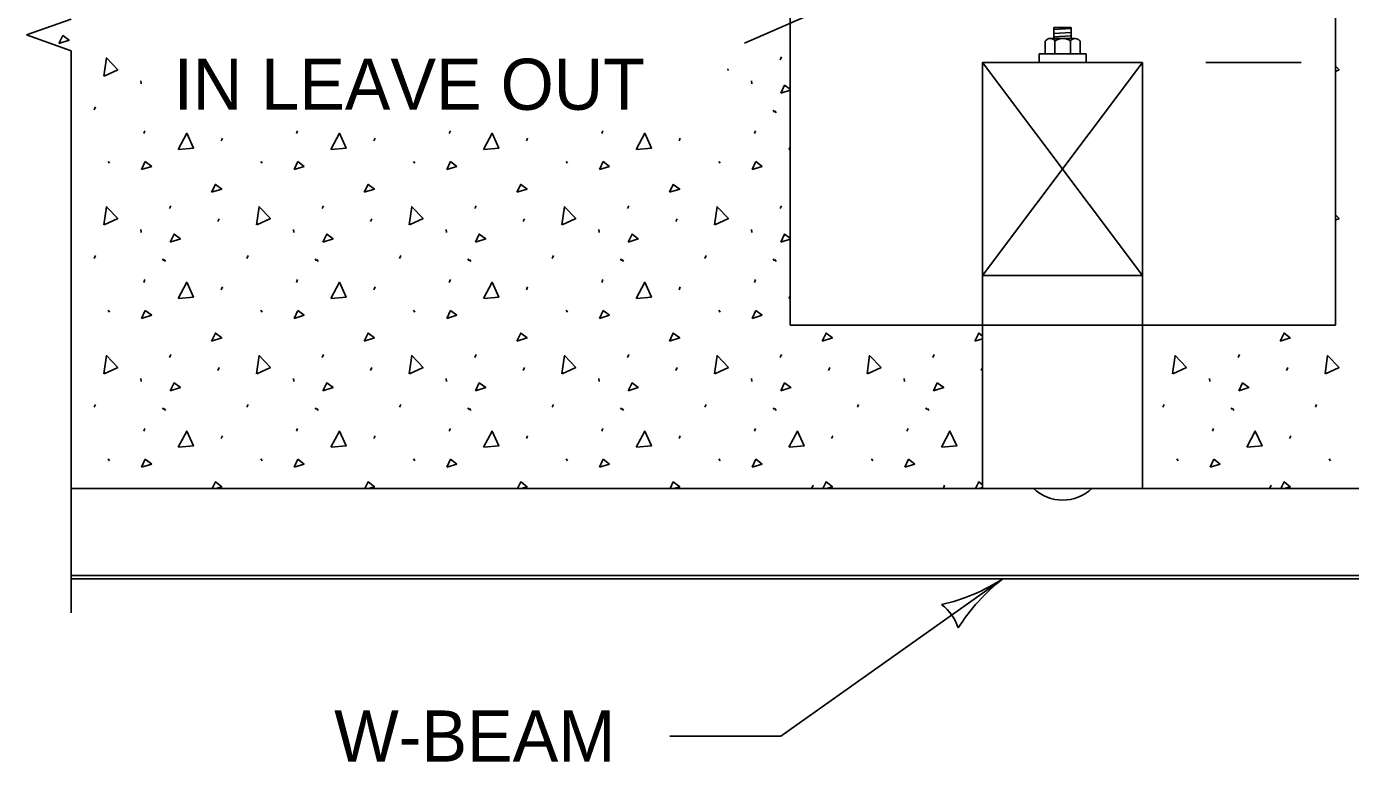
# Model space of a CAD drawing. Extents: x 49991.4 to 50021, y 49987.6 to 50011.4.
# Drawn here: x 50009.655 to 50011.209, y 49995.289 to 49996.152 of the extents above; entities that cross this region are included whole.
import ezdxf

# ---------------------------------------------------------------- set-up
doc = ezdxf.new("R2010")
doc.units = 0
for name, color, linetype in [('Level 1', 7, 'Continuous'), ('Level 2', 7, 'Continuous'), ('Level 3', 7, 'Continuous'), ('Level 4', 7, 'Continuous'), ('Level 6', 7, 'Continuous')]:
    doc.layers.add(name, color=color, linetype=linetype)

msp = doc.modelspace()

# ---------------------------------------------------------------- linework, layer by layer
at = {"layer": 'Level 1'}
for p, q in [((50010.5512, 49996.1214), (50010.5512, 49996.4414)), ((50011.1912, 49996.1214), (50011.1912, 49996.4414)), ((50010.8813, 49996.1506), (50010.8607, 49996.1506)), ((50010.8607, 49996.1379), (50010.8607, 49996.1506)), ((50010.8813, 49996.1494), (50010.8607, 49996.1484)), ((50010.8813, 49996.1378), (50010.8813, 49996.1506)), ((50010.8507, 49996.1198), (50010.8507, 49996.1348)), ((50010.8859, 49996.1378), (50010.8565, 49996.1379)), ((50010.8813, 49996.1449), (50010.8607, 49996.1438)), ((50010.8813, 49996.1408), (50010.8607, 49996.1398)), ((50010.8621, 49996.1198), (50010.8621, 49996.1349)), ((50010.8803, 49996.1198), (50010.8803, 49996.135)), ((50010.8915, 49996.1352), (50010.8915, 49996.1198)), ((50010.5396, 49996.1128), (50010.5411, 49996.1162)), ((50010.5512, 49996.1214), (50010.5512, 49995.8014)), ((50010.8986, 49996.1198), (50010.8436, 49996.1198)), ((50010.8436, 49996.1198), (50010.8436, 49996.1097)), ((50010.8986, 49996.1198), (50010.8986, 49996.1097)), ((50011.1912, 49996.1214), (50011.1912, 49995.8014)), ((50010.7772, 49995.6094), (50010.7772, 49996.1097)), ((50010.9648, 49996.1097), (50010.7772, 49996.1097)), ((50010.7772, 49996.1097), (50010.9648, 49995.8595)), ((50010.9648, 49996.1097), (50010.7772, 49995.8595)), ((50010.9648, 49995.6094), (50010.9648, 49996.1097)), ((50009.7892, 49996.0881), (50009.7896, 49996.0848)), ((50010.5058, 49996.0881), (50010.5062, 49996.0848)), ((50010.5512, 49996.077), (50010.5404, 49996.0736)), ((50009.7345, 49996.0542), (50009.736, 49996.0576)), ((50010.5313, 49996.0537), (50010.5328, 49996.0515)), ((50010.5333, 49996.0529), (50010.5348, 49996.0507)), ((50009.7926, 49996.0261), (50009.7941, 49996.0295)), ((50009.8834, 49996.0175), (50009.8849, 49996.0209)), ((50009.9718, 49996.0261), (50009.9733, 49996.0295)), ((50010.0626, 49996.0175), (50010.0641, 49996.0209)), ((50010.151, 49996.0261), (50010.1525, 49996.0295)), ((50010.2417, 49996.0175), (50010.2432, 49996.0209)), ((50010.3301, 49996.0261), (50010.3316, 49996.0295)), ((50010.4209, 49996.0175), (50010.4224, 49996.0209)), ((50010.5093, 49996.0261), (50010.5108, 49996.0295)), ((50010.5497, 49996.0074), (50010.5512, 49996.0104)), ((50010.5512, 49996.0075), (50010.5501, 49996.0074)), ((50009.7509, 49995.9936), (50009.7524, 49995.9914)), ((50009.79, 49995.9839), (50009.7945, 49995.9933)), ((50009.7945, 49995.9933), (50009.802, 49995.9877)), ((50009.93, 49995.9936), (50009.9315, 49995.9914)), ((50009.9692, 49995.9839), (50009.9737, 49995.9933)), ((50009.9737, 49995.9933), (50009.9811, 49995.9877)), ((50010.1092, 49995.9936), (50010.1107, 49995.9914)), ((50010.1483, 49995.9839), (50010.1528, 49995.9933)), ((50010.1528, 49995.9933), (50010.1603, 49995.9877)), ((50010.2883, 49995.9936), (50010.2898, 49995.9914)), ((50010.3275, 49995.9839), (50010.332, 49995.9933)), ((50010.332, 49995.9933), (50010.3394, 49995.9877)), ((50010.4675, 49995.9936), (50010.469, 49995.9914)), ((50010.5067, 49995.9839), (50010.5111, 49995.9933)), ((50010.5111, 49995.9933), (50010.5186, 49995.9877)), ((50009.802, 49995.9877), (50009.79, 49995.9839)), ((50009.9811, 49995.9877), (50009.9692, 49995.9839)), ((50010.1603, 49995.9877), (50010.1483, 49995.9839)), ((50010.3394, 49995.9877), (50010.3275, 49995.9839)), ((50010.5186, 49995.9877), (50010.5067, 49995.9839)), ((50009.823, 49995.9381), (50009.8245, 49995.9414)), ((50010.0021, 49995.9381), (50010.0036, 49995.9414)), ((50010.1813, 49995.9381), (50010.1828, 49995.9414)), ((50010.3605, 49995.9381), (50010.362, 49995.9414)), ((50010.5396, 49995.9381), (50010.5411, 49995.9414)), ((50009.7892, 49995.9134), (50009.7896, 49995.9101)), ((50009.8797, 49995.9228), (50009.8812, 49995.9261)), ((50009.9684, 49995.9134), (50009.9687, 49995.9101)), ((50010.0588, 49995.9228), (50010.0603, 49995.9261)), ((50010.1475, 49995.9134), (50010.1479, 49995.9101)), ((50010.238, 49995.9228), (50010.2395, 49995.9261)), ((50010.3267, 49995.9134), (50010.327, 49995.9101)), ((50010.4172, 49995.9228), (50010.4186, 49995.9261)), ((50010.5058, 49995.9134), (50010.5062, 49995.9101)), ((50010.5512, 49995.9023), (50010.5404, 49995.8989)), ((50009.7345, 49995.8795), (50009.736, 49995.8829)), ((50009.9136, 49995.8795), (50009.9151, 49995.8829)), ((50010.0928, 49995.8795), (50010.0943, 49995.8829)), ((50010.2719, 49995.8795), (50010.2734, 49995.8829)), ((50010.4511, 49995.8795), (50010.4526, 49995.8829)), ((50009.8146, 49995.879), (50009.8161, 49995.8768)), ((50009.8166, 49995.8782), (50009.8181, 49995.8759)), ((50009.9938, 49995.879), (50009.9953, 49995.8768)), ((50009.9958, 49995.8782), (50009.9973, 49995.8759)), ((50010.173, 49995.879), (50010.1745, 49995.8768)), ((50010.175, 49995.8782), (50010.1765, 49995.8759)), ((50010.3521, 49995.879), (50010.3536, 49995.8768)), ((50010.3541, 49995.8782), (50010.3556, 49995.8759)), ((50010.5313, 49995.879), (50010.5328, 49995.8768)), ((50010.5333, 49995.8782), (50010.5348, 49995.8759)), ((50009.7926, 49995.8514), (50009.7941, 49995.8547)), ((50009.9718, 49995.8514), (50009.9733, 49995.8547)), ((50010.151, 49995.8514), (50010.1525, 49995.8547)), ((50010.3301, 49995.8514), (50010.3316, 49995.8547)), ((50010.5093, 49995.8514), (50010.5108, 49995.8547)), ((50010.9648, 49995.8595), (50010.7772, 49995.8595)), ((50009.8834, 49995.8428), (50009.8849, 49995.8462)), ((50010.0626, 49995.8428), (50010.0641, 49995.8462)), ((50010.2417, 49995.8428), (50010.2432, 49995.8462)), ((50010.4209, 49995.8428), (50010.4224, 49995.8462)), ((50010.5497, 49995.8327), (50010.5512, 49995.8357)), ((50009.7509, 49995.8189), (50009.7524, 49995.8167)), ((50009.93, 49995.8189), (50009.9315, 49995.8167)), ((50010.1092, 49995.8189), (50010.1107, 49995.8167)), ((50010.2883, 49995.8189), (50010.2898, 49995.8167)), ((50010.4675, 49995.8189), (50010.469, 49995.8167)), ((50010.5512, 49995.8328), (50010.5501, 49995.8327)), ((50009.79, 49995.8092), (50009.7945, 49995.8186)), ((50009.802, 49995.813), (50009.79, 49995.8092)), ((50009.7945, 49995.8186), (50009.802, 49995.813)), ((50009.9692, 49995.8092), (50009.9737, 49995.8186)), ((50009.9811, 49995.813), (50009.9692, 49995.8092)), ((50009.9737, 49995.8186), (50009.9811, 49995.813)), ((50010.1483, 49995.8092), (50010.1528, 49995.8186)), ((50010.1603, 49995.813), (50010.1483, 49995.8092)), ((50010.1528, 49995.8186), (50010.1603, 49995.813)), ((50010.3275, 49995.8092), (50010.332, 49995.8186)), ((50010.3394, 49995.813), (50010.3275, 49995.8092)), ((50010.332, 49995.8186), (50010.3394, 49995.813)), ((50010.5067, 49995.8092), (50010.5111, 49995.8186)), ((50010.5186, 49995.813), (50010.5067, 49995.8092)), ((50010.5111, 49995.8186), (50010.5186, 49995.813)), ((50010.7772, 49995.8014), (50010.5512, 49995.8014)), ((50010.9648, 49995.8014), (50011.1912, 49995.8014)), ((50010.9648, 49995.6121), (50010.9648, 49995.7954)), ((50010.7772, 49995.7854), (50010.7681, 49995.7826)), ((50009.823, 49995.7634), (50009.8245, 49995.7667)), ((50010.0021, 49995.7634), (50010.0036, 49995.7667)), ((50010.1813, 49995.7634), (50010.1828, 49995.7667)), ((50010.3605, 49995.7634), (50010.362, 49995.7667)), ((50010.5396, 49995.7634), (50010.5411, 49995.7667)), ((50010.7188, 49995.7634), (50010.7203, 49995.7667)), ((50011.0771, 49995.7634), (50011.0786, 49995.7667)), ((50009.8797, 49995.7481), (50009.8812, 49995.7514)), ((50010.0588, 49995.7481), (50010.0603, 49995.7514)), ((50010.238, 49995.7481), (50010.2395, 49995.7514)), ((50010.4172, 49995.7481), (50010.4186, 49995.7514)), ((50010.5963, 49995.7481), (50010.5978, 49995.7514)), ((50010.7755, 49995.7481), (50010.777, 49995.7514)), ((50011.1338, 49995.7481), (50011.1353, 49995.7514)), ((50009.7892, 49995.7387), (50009.7896, 49995.7353)), ((50009.9684, 49995.7387), (50009.9687, 49995.7353)), ((50010.1475, 49995.7387), (50010.1479, 49995.7353)), ((50010.3267, 49995.7387), (50010.327, 49995.7353)), ((50010.5058, 49995.7387), (50010.5062, 49995.7353)), ((50010.685, 49995.7387), (50010.6854, 49995.7353)), ((50011.0433, 49995.7387), (50011.0437, 49995.7353)), ((50009.7345, 49995.7048), (50009.736, 49995.7082)), ((50009.8146, 49995.7043), (50009.8161, 49995.7021)), ((50009.8166, 49995.7034), (50009.8181, 49995.7012)), ((50009.9136, 49995.7048), (50009.9151, 49995.7082)), ((50009.9938, 49995.7043), (50009.9953, 49995.7021)), ((50009.9958, 49995.7034), (50009.9973, 49995.7012)), ((50010.0928, 49995.7048), (50010.0943, 49995.7082)), ((50010.173, 49995.7043), (50010.1745, 49995.7021)), ((50010.175, 49995.7034), (50010.1765, 49995.7012)), ((50010.2719, 49995.7048), (50010.2734, 49995.7082)), ((50010.3521, 49995.7043), (50010.3536, 49995.7021)), ((50010.3541, 49995.7034), (50010.3556, 49995.7012)), ((50010.4511, 49995.7048), (50010.4526, 49995.7082)), ((50010.5313, 49995.7043), (50010.5328, 49995.7021)), ((50010.5333, 49995.7034), (50010.5348, 49995.7012)), ((50010.6303, 49995.7048), (50010.6317, 49995.7082)), ((50010.7104, 49995.7043), (50010.7119, 49995.7021)), ((50010.7124, 49995.7034), (50010.7139, 49995.7012)), ((50010.9886, 49995.7048), (50010.9901, 49995.7082)), ((50011.0688, 49995.7043), (50011.0703, 49995.7021)), ((50011.0708, 49995.7034), (50011.0722, 49995.7012)), ((50011.1677, 49995.7048), (50011.1692, 49995.7082)), ((50009.7926, 49995.6767), (50009.7941, 49995.68)), ((50009.9718, 49995.6767), (50009.9733, 49995.68)), ((50010.151, 49995.6767), (50010.1525, 49995.68)), ((50010.3301, 49995.6767), (50010.3316, 49995.68)), ((50010.5093, 49995.6767), (50010.5108, 49995.68)), ((50010.6884, 49995.6767), (50010.6899, 49995.68)), ((50011.0468, 49995.6767), (50011.0482, 49995.68)), ((50009.8834, 49995.6681), (50009.8849, 49995.6714)), ((50010.0626, 49995.6681), (50010.0641, 49995.6714)), ((50010.2417, 49995.6681), (50010.2432, 49995.6714)), ((50010.4209, 49995.6681), (50010.4224, 49995.6714)), ((50010.6, 49995.6681), (50010.6015, 49995.6714)), ((50011.1375, 49995.6681), (50011.139, 49995.6714)), ((50009.7509, 49995.6442), (50009.7524, 49995.642)), ((50009.79, 49995.6345), (50009.7945, 49995.6438)), ((50009.802, 49995.6382), (50009.79, 49995.6345)), ((50009.7945, 49995.6438), (50009.802, 49995.6382)), ((50009.93, 49995.6442), (50009.9315, 49995.642)), ((50009.9692, 49995.6345), (50009.9737, 49995.6438)), ((50009.9811, 49995.6382), (50009.9692, 49995.6345)), ((50009.9737, 49995.6438), (50009.9811, 49995.6382)), ((50010.1092, 49995.6442), (50010.1107, 49995.642)), ((50010.1483, 49995.6345), (50010.1528, 49995.6438)), ((50010.1603, 49995.6382), (50010.1483, 49995.6345)), ((50010.1528, 49995.6438), (50010.1603, 49995.6382)), ((50010.2883, 49995.6442), (50010.2898, 49995.642)), ((50010.3275, 49995.6345), (50010.332, 49995.6438)), ((50010.3394, 49995.6382), (50010.3275, 49995.6345)), ((50010.332, 49995.6438), (50010.3394, 49995.6382)), ((50010.4675, 49995.6442), (50010.469, 49995.642)), ((50010.5067, 49995.6345), (50010.5111, 49995.6438)), ((50010.5186, 49995.6382), (50010.5067, 49995.6345)), ((50010.5111, 49995.6438), (50010.5186, 49995.6382)), ((50010.6467, 49995.6442), (50010.6482, 49995.642)), ((50010.6858, 49995.6345), (50010.6903, 49995.6438)), ((50010.6978, 49995.6382), (50010.6858, 49995.6345)), ((50010.6903, 49995.6438), (50010.6978, 49995.6382)), ((50011.005, 49995.6442), (50011.0065, 49995.642)), ((50011.0441, 49995.6345), (50011.0486, 49995.6438)), ((50011.0561, 49995.6382), (50011.0441, 49995.6345)), ((50011.0486, 49995.6438), (50011.0561, 49995.6382)), ((50011.1841, 49995.6442), (50011.1856, 49995.642)), ((50009.9073, 49995.6094), (50009.7073, 49995.6094)), ((50009.9073, 49995.6094), (50011.8351, 49995.6094)), ((50010.5769, 49995.61), (50010.5784, 49995.6134)), ((50010.7311, 49995.61), (50010.7326, 49995.6134)), ((50010.7772, 49995.6107), (50010.7731, 49995.6094)), ((50011.1144, 49995.61), (50011.1159, 49995.6134)), ((50009.7073, 49995.5073), (50012.0351, 49995.5073)), ((50009.7073, 49995.5034), (50012.0351, 49995.5034))]:
    msp.add_line(p, q, dxfattribs=at)
for points in [[(50009.6931, 49996.132), (50009.6976, 49996.1413), (50009.7051, 49996.1357), (50009.6931, 49996.132)], [(50009.7459, 49996.0936), (50009.7488, 49996.115), (50009.7622, 49996.1012), (50009.7462, 49996.0938)], [(50010.4779, 49996.1021), (50010.4788, 49996.1012), (50010.4779, 49996.1007)], [(50011.1912, 49996.1055), (50011.1955, 49996.1012), (50011.1912, 49996.0992)], [(50010.5404, 49996.0736), (50010.5448, 49996.083), (50010.5512, 49996.0782)], [(50009.8331, 49996.0074), (50009.8431, 49996.0265), (50009.851, 49996.0089), (50009.8334, 49996.0074)], [(50010.0122, 49996.0074), (50010.0223, 49996.0265), (50010.0301, 49996.0089), (50010.0126, 49996.0074)], [(50010.1914, 49996.0074), (50010.2014, 49996.0265), (50010.2093, 49996.0089), (50010.1917, 49996.0074)], [(50010.3705, 49996.0074), (50010.3806, 49996.0265), (50010.3884, 49996.0089), (50010.3709, 49996.0074)], [(50009.8723, 49995.9573), (50009.8768, 49995.9666), (50009.8842, 49995.961), (50009.8723, 49995.9573)], [(50010.0515, 49995.9573), (50010.0559, 49995.9666), (50010.0634, 49995.961), (50010.0515, 49995.9573)], [(50010.2306, 49995.9573), (50010.2351, 49995.9666), (50010.2425, 49995.961), (50010.2306, 49995.9573)], [(50010.4098, 49995.9573), (50010.4142, 49995.9666), (50010.4217, 49995.961), (50010.4098, 49995.9573)], [(50009.7459, 49995.9189), (50009.7488, 49995.9402), (50009.7622, 49995.9264), (50009.7462, 49995.919)], [(50009.9251, 49995.9189), (50009.928, 49995.9402), (50009.9414, 49995.9264), (50009.9254, 49995.919)], [(50010.1042, 49995.9189), (50010.1072, 49995.9402), (50010.1205, 49995.9264), (50010.1046, 49995.919)], [(50010.2834, 49995.9189), (50010.2863, 49995.9402), (50010.2997, 49995.9264), (50010.2837, 49995.919)], [(50010.4625, 49995.9189), (50010.4655, 49995.9402), (50010.4788, 49995.9264), (50010.4629, 49995.919)], [(50011.1912, 49995.9308), (50011.1955, 49995.9264), (50011.1912, 49995.9245)], [(50009.8237, 49995.8989), (50009.8282, 49995.9082), (50009.8357, 49995.9026), (50009.8237, 49995.8989)], [(50010.0029, 49995.8989), (50010.0074, 49995.9082), (50010.0148, 49995.9026), (50010.0029, 49995.8989)], [(50010.1821, 49995.8989), (50010.1865, 49995.9082), (50010.194, 49995.9026), (50010.1821, 49995.8989)], [(50010.3612, 49995.8989), (50010.3657, 49995.9082), (50010.3731, 49995.9026), (50010.3612, 49995.8989)], [(50010.5404, 49995.8989), (50010.5448, 49995.9082), (50010.5512, 49995.9034)], [(50009.8331, 49995.8327), (50009.8431, 49995.8517), (50009.851, 49995.8342), (50009.8334, 49995.8327)], [(50010.0122, 49995.8327), (50010.0223, 49995.8517), (50010.0301, 49995.8342), (50010.0126, 49995.8327)], [(50010.1914, 49995.8327), (50010.2014, 49995.8517), (50010.2093, 49995.8342), (50010.1917, 49995.8327)], [(50010.3705, 49995.8327), (50010.3806, 49995.8517), (50010.3884, 49995.8342), (50010.3709, 49995.8327)], [(50009.8723, 49995.7826), (50009.8768, 49995.7919), (50009.8842, 49995.7863), (50009.8723, 49995.7826)], [(50010.0515, 49995.7826), (50010.0559, 49995.7919), (50010.0634, 49995.7863), (50010.0515, 49995.7826)], [(50010.2306, 49995.7826), (50010.2351, 49995.7919), (50010.2425, 49995.7863), (50010.2306, 49995.7826)], [(50010.4098, 49995.7826), (50010.4142, 49995.7919), (50010.4217, 49995.7863), (50010.4098, 49995.7826)], [(50010.5889, 49995.7826), (50010.5934, 49995.7919), (50010.6009, 49995.7863), (50010.5889, 49995.7826)], [(50010.7681, 49995.7826), (50010.7726, 49995.7919), (50010.7772, 49995.7884)], [(50011.1264, 49995.7826), (50011.1309, 49995.7919), (50011.1383, 49995.7863), (50011.1264, 49995.7826)], [(50009.7459, 49995.7442), (50009.7488, 49995.7655), (50009.7622, 49995.7517), (50009.7462, 49995.7443)], [(50009.9251, 49995.7442), (50009.928, 49995.7655), (50009.9414, 49995.7517), (50009.9254, 49995.7443)], [(50010.1042, 49995.7442), (50010.1072, 49995.7655), (50010.1205, 49995.7517), (50010.1046, 49995.7443)], [(50010.2834, 49995.7442), (50010.2863, 49995.7655), (50010.2997, 49995.7517), (50010.2837, 49995.7443)], [(50010.4625, 49995.7442), (50010.4655, 49995.7655), (50010.4788, 49995.7517), (50010.4629, 49995.7443)], [(50010.6417, 49995.7442), (50010.6446, 49995.7655), (50010.658, 49995.7517), (50010.642, 49995.7443)], [(50011, 49995.7442), (50011.003, 49995.7655), (50011.0163, 49995.7517), (50011.0004, 49995.7443)], [(50011.1792, 49995.7442), (50011.1821, 49995.7655), (50011.1955, 49995.7517), (50011.1795, 49995.7443)], [(50009.8237, 49995.7242), (50009.8282, 49995.7335), (50009.8357, 49995.7279), (50009.8237, 49995.7242)], [(50010.0029, 49995.7242), (50010.0074, 49995.7335), (50010.0148, 49995.7279), (50010.0029, 49995.7242)], [(50010.1821, 49995.7242), (50010.1865, 49995.7335), (50010.194, 49995.7279), (50010.1821, 49995.7242)], [(50010.3612, 49995.7242), (50010.3657, 49995.7335), (50010.3731, 49995.7279), (50010.3612, 49995.7242)], [(50010.5404, 49995.7242), (50010.5448, 49995.7335), (50010.5523, 49995.7279), (50010.5404, 49995.7242)], [(50010.7195, 49995.7242), (50010.724, 49995.7335), (50010.7315, 49995.7279), (50010.7195, 49995.7242)], [(50011.0778, 49995.7242), (50011.0823, 49995.7335), (50011.0898, 49995.7279), (50011.0778, 49995.7242)], [(50009.8331, 49995.658), (50009.8431, 49995.677), (50009.851, 49995.6595), (50009.8334, 49995.658)], [(50010.0122, 49995.658), (50010.0223, 49995.677), (50010.0301, 49995.6595), (50010.0126, 49995.658)], [(50010.1914, 49995.658), (50010.2014, 49995.677), (50010.2093, 49995.6595), (50010.1917, 49995.658)], [(50010.3705, 49995.658), (50010.3806, 49995.677), (50010.3884, 49995.6595), (50010.3709, 49995.658)], [(50010.5497, 49995.658), (50010.5598, 49995.677), (50010.5676, 49995.6595), (50010.5501, 49995.658)], [(50010.7289, 49995.658), (50010.7389, 49995.677), (50010.7468, 49995.6595), (50010.7292, 49995.658)], [(50011.0872, 49995.658), (50011.0972, 49995.677), (50011.1051, 49995.6595), (50011.0875, 49995.658)], [(50009.873, 49995.6094), (50009.8768, 49995.6172), (50009.8842, 49995.6116), (50009.8773, 49995.6094)], [(50010.0522, 49995.6094), (50010.0559, 49995.6172), (50010.0634, 49995.6116), (50010.0565, 49995.6094)], [(50010.2314, 49995.6094), (50010.2351, 49995.6172), (50010.2425, 49995.6116), (50010.2356, 49995.6094)], [(50010.4105, 49995.6094), (50010.4142, 49995.6172), (50010.4217, 49995.6116), (50010.4148, 49995.6094)], [(50010.5897, 49995.6094), (50010.5934, 49995.6172), (50010.6009, 49995.6116), (50010.594, 49995.6094)], [(50010.7688, 49995.6094), (50010.7726, 49995.6172), (50010.7772, 49995.6137)], [(50011.1272, 49995.6094), (50011.1309, 49995.6172), (50011.1383, 49995.6116), (50011.1314, 49995.6094)]]:
    msp.add_lwpolyline(points, dxfattribs=at)
for centre, major_axis, start_param, end_param in [((50010.8565, 49996.1311), (0.00683, 0), 0.591441, 2.573965), ((50010.8713, 49996.1224), (-0.0156, 0), 4.094675, 5.339631), ((50010.8859, 49996.1308), (-0.00704, 0), 3.808999, 5.646245)]:
    msp.add_ellipse(centre, major_axis=major_axis, ratio=0.991667, start_param=start_param, end_param=end_param, dxfattribs=at)
at = {"layer": 'Level 3'}
for p, q in [((50010.8713, 49996.296), (50010.4979, 49996.1323)), ((50011.1512, 49996.1097), (50011.0391, 49996.1097)), ((50010.5404, 49995.3189), (50010.8008, 49995.5034)), ((50010.41, 49995.3189), (50010.5404, 49995.3189))]:
    msp.add_line(p, q, dxfattribs=at)
for centre, radius, start, end in [((50010.6799, 49995.69), 0.2223, 282.7682, 302.9517), ((50010.9447, 49995.3202), 0.233, 128.1395, 147.3894), ((50010.6962, 49995.4293), 0.0548, 17.451, 53.1734)]:
    msp.add_arc(centre, radius, start, end, dxfattribs=at)
at = {"layer": 'Level 4'}
msp.add_line((50010.7772, 49995.8014), (50010.9648, 49995.8014), dxfattribs=at)
msp.add_ellipse((50010.8712, 49995.6451), major_axis=(0.0497, 0), ratio=0.991667, start_param=3.94982, end_param=5.474958, dxfattribs=at)
at = {"layer": 'Level 6'}
for p, q in [((50009.7073, 49996.1606), (50009.655, 49996.1421)), ((50009.7073, 49996.1235), (50009.655, 49996.1421)), ((50009.7073, 49996.1235), (50009.7073, 49996.0056)), ((50009.7073, 49996.0056), (50009.7073, 49995.4634))]:
    msp.add_line(p, q, dxfattribs=at)

# ---------------------------------------------------------------- texts
at = {"layer": 'Level 2'}
for s, p in [('IN LEAVE OUT', (50009.828, 49996.0541)), ('W-BEAM', (50010.0162, 49995.2889))]:
    msp.add_text(s, height=0.06, dxfattribs=at).set_placement(p)

doc.saveas('drawing.dxf')
